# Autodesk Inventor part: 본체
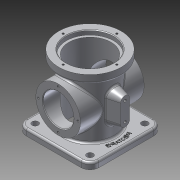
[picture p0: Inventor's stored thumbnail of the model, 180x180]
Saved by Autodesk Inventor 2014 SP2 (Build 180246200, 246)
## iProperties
Created: 2021-03
Part Number: 본체
Material: 알루미늄 6061
Document SubType Name: Modeling
Designer: 거성
Density: 2.71 g/cm^3
Appearance: 알루미늄 - 평지
Author: 거성
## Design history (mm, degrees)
sketch "스케치1"
  geometry: L1 (57, 57)-(-57, 57); L2 (-57, 57)-(-57, -57); L3 (-57, -57)-(57, -57); L4 (57, -57)-(57, 57); L5 (57, 57)-(-57, -57); L6 (-57, 57)-(57, -57); 1 further point
  constraints: 12 end point, 2 midpoint, 2 parallel, 1 horizontal, 1 perpendicular
  dimensions: "d0" = 114 distance of L3.end L2.end; "d1" = 114 distance of L2.end L1.end
extrude "돌출1" new body sketch "스케치1" stored distance "d2" = 10; taper "d3" = 0 deg
sketch "스케치2"
  geometry: C1 r 38 at (0, 0); 1 further point
  constraints: 1 centre point, 1 coincident
  dimensions: "d4" = 76 diameter of C1
extrude "돌출2" join sketch "스케치2" distance "d5" = 101; taper "d6" = 0 deg
sketch "스케치3"
  geometry: C1 r 38 at (0, 0) reference; C2 r 49 at (0, 0)
  constraints: 1 centre point, 1 coincident
  dimensions: "d7" = 98 diameter of C2
extrude "돌출3" join sketch "스케치3" distance "d8" = 13; taper "d9" = 0 deg
sketch "스케치4"
  geometry: C1 r 49 at (0, 0) reference; 1 further point
  constraints: 1 coincident
hole "구멍1" sketch "스케치4" at (0, 0) diameter "d10" = 66; stored, may be unused: countersink angle "d14" = 90 deg, drill point angle "d16" = 118 deg; dims "d11" = 6, "d12" = 74, "d13" = 7, "d15" = 8
node "작업 평면1"
sketch "스케치5"
  geometry: L1 (57, -5)-(-57, -5) reference; C1 r 35 at (0, 49); 2 further points
  constraints: 1 centre point, 1 midpoint, 1 vertical alignment
  dimensions: "d18" = 70 diameter of C1; "d19" = 54 distance from line of L1 C1.centre
extrude "돌출4" join sketch "스케치5" stored distance "d20" = 13; taper "d21" = 0 deg
sketch "스케치6"
  geometry: C1 r 35 at (0, 0) reference; 2 further points
  constraints: 1 coincident
hole "구멍2" sketch "스케치6" at (0, 0) diameter "d22" = 48; stored, may be unused: countersink angle "d26" = 90 deg, drill point angle "d28" = 118 deg; dims "d23" = 6, "d24" = 74, "d25" = 7, "d27" = 8
fillet "모깎기1" dims "d29" = 14, "d30" = 3
fillet "모깎기2" dims "d31" = 3
sketch "스케치7" dims "d32" = 62
  geometry: C1 r 35 at (0, 0) reference; 3 further points
  constraints: 2 vertical alignment, 1 coincident, 2 other
hole "구멍3" sketch "스케치7" at (0, 31) diameter "d33" = 3.242; stored, may be unused: countersink angle "d37" = 90 deg, drill point angle "d39" = 118 deg; dims "d34" = 6, "d35" = 74, "d36" = 7, "d38" = 8
sketch "스케치8" dims "d43" = 84
  geometry: C1 r 49 at (0, 0) reference; 2 further points
  constraints: 2 vertical alignment, 1 coincident, 2 other
hole "구멍4" sketch "스케치8" at (0, 42) diameter "d44" = 3.242; stored, may be unused: countersink angle "d48" = 90 deg, drill point angle "d50" = 118 deg; dims "d45" = 6, "d46" = 74, "d47" = 7, "d49" = 8
chamfer "모따기1" distance "d54" = 1; stored, may be unused: second distance "d55" = 2, angle "d56" = 45 deg
node "작업 평면2"
sketch "스케치9"
  geometry: L1 (63.5, 0)-(34.5, 0); L2 (63.5, 7)-(34.5, 7); L3 (34.5, -7)-(63.5, -7); L4 (-5, -43)-(-5, 43) reference; L5 (14, -50)-(84, -50) reference; A1 r 7 centre (63.5, 0) between (63.5, -7) and (63.5, 7); A2 r 7 centre (34.5, 0) between (34.5, 7) and (34.5, -7); 2 further points
  constraints: 8 end point, 4 point on circle, 4 tangent, 2 centre point, 1 horizontal, 1 midpoint, 1 parallel
  dimensions: "d59" = 54 distance from line of L4 point (49, 0); "d60" = 14 distance between parallel lines of L3 L2; "d61" = 43 dimension on A2 A1; "d82" = 50 distance from line of point (49, 0) L5
extrude "돌출5" join sketch "스케치9" distance "d62" = 20; taper "d63" = 15 deg
sketch "스케치10"
  geometry: A1 r 11 centre (43, -43) between (43, -54) and (54, -43) reference; A2 r 11 centre (43, 43) between (54, 43) and (43, 54) reference; A3 r 11 centre (-43, 43) between (-43, 54) and (-54, 43) reference; A4 r 11 centre (-43, -43) between (-54, -43) and (-43, -54) reference; 4 further points
  constraints: 4 coincident
hole "구멍5" sketch "스케치10" at (-43, 43), (43, 43), (43, -43), (-43, -43) diameter "d64" = 10; stored, may be unused: countersink angle "d68" = 90 deg, drill point angle "d70" = 118 deg; dims "d65" = 6, "d66" = 74, "d67" = 7, "d69" = 8
fillet "모깎기3" dims "d71" = 3
sketch "스케치11"
  geometry: A1 r 7 centre (0, 34.5) between (-7, 34.5) and (7, 34.5) reference; A2 r 7 centre (0, 63.5) between (7, 63.5) and (-7, 63.5) reference; 3 further points
  constraints: 2 coincident
hole "구멍6" sketch "스케치11" at (0, 63.5), (0, 34.5) diameter "d72" = 4.134; stored, may be unused: countersink angle "d76" = 90 deg, drill point angle "d78" = 118 deg; dims "d73" = 8, "d74" = 74, "d75" = 7, "d77" = 10
sketch "스케치12"
  geometry: C1 r 41 at (0, 0) reference; C2 r 50 at (0, 0)
  constraints: 1 centre point, 1 coincident, 1 other
  dimensions: "d79" = 100 diameter of C2
feature "엠보싱1" sketch "스케치12" dims "d0" = 114, "d1" = 114, "d80" = 0.5, "d81" = 0
node "솔리드1"
mirror "대칭1"
pattern_circular "원형 패턴1" dims angle "d41" = 360 deg
mirror "대칭2"
pattern_circular "원형 패턴2" dims angle "d52" = 360 deg
other parameters: "d57" = 55
